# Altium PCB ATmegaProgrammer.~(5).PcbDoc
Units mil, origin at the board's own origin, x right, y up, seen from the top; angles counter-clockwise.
Board outline 6000 x 4000 mil, 2 copper layers (Top Layer, Bottom Layer); 9 components, 8 nets, 64 pads, 0 vias.
Unrouted connection lines stored in the file: 16.
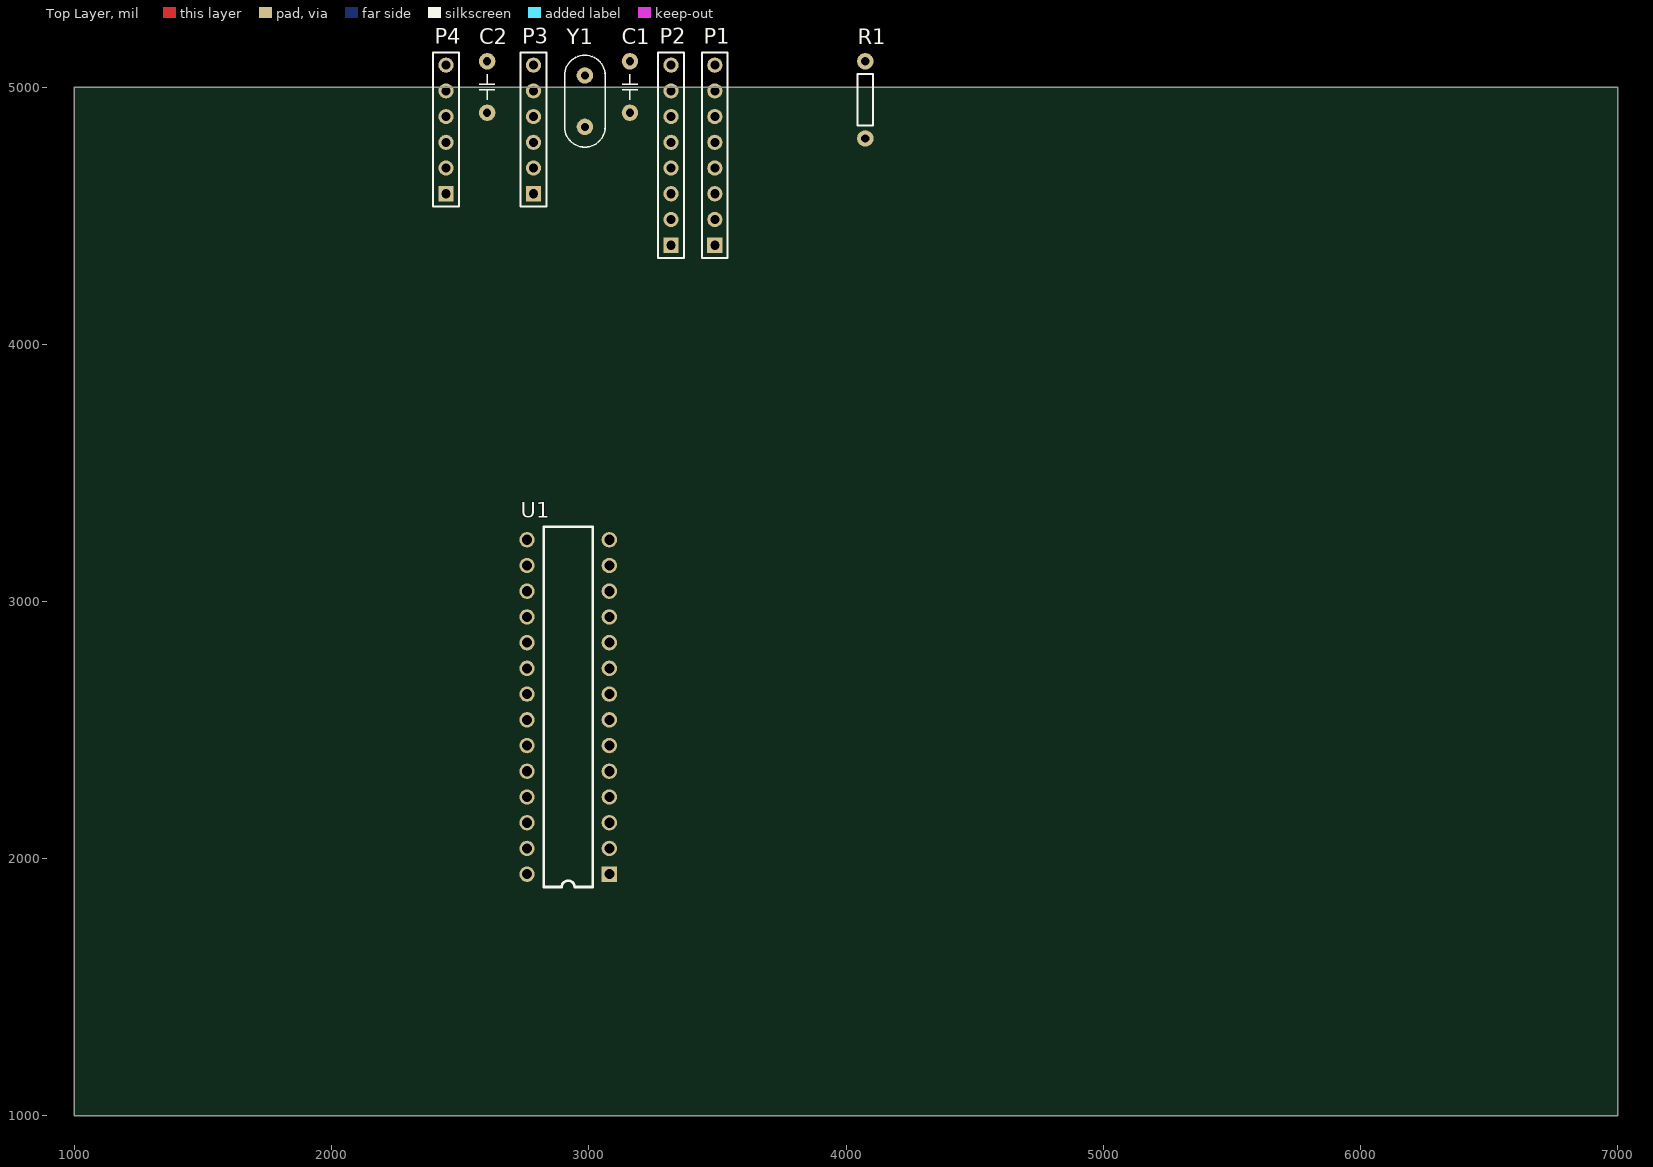
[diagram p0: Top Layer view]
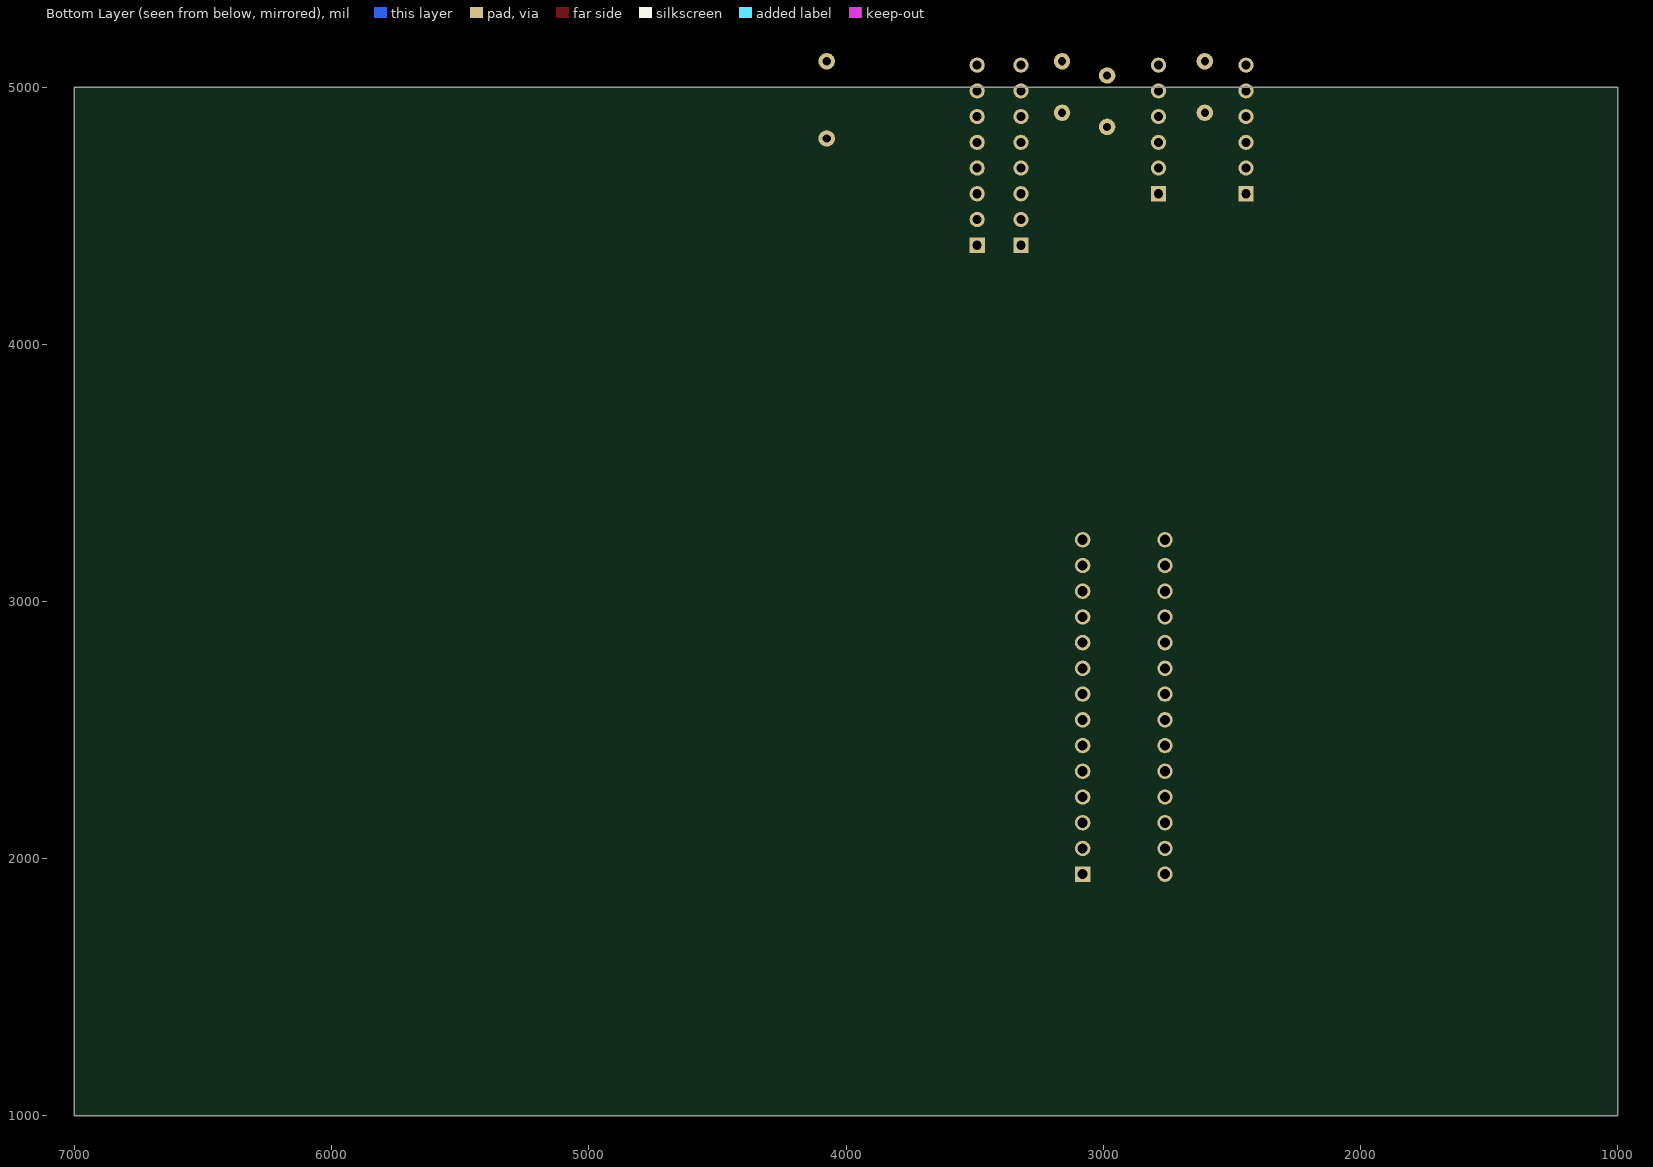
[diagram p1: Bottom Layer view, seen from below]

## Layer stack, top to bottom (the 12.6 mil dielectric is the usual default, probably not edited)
Top Layer: signal copper 1.4
Dielectric: dielectric 12.6, FR-4, Dk 4.8
Bottom Layer: signal copper 1.4

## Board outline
1000,1000 7000,1000 7000,5000 1000,5000

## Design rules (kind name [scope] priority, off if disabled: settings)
Clearance [All] p1: gap=10
PolygonConnect [All] p1: connectstyle=Relief reliefconductorwidth=10 reliefentries=4 polygonreliefangle="90 Angle"
RoomDefinition ATmegaProgrammer [InComponentClass('ATmegaProgrammer')] p1: confinementstyle=ConfineIn formatcopy=TRUE lockcomponents=FALSE outline 2385,3725 4145,3725 4145,5245 2385,5245
RoutingVias [All] p1: holewidth=28 width=50 viastyle="Through Hole" minholewidth=28 minwidth=50 maxholewidth=28 maxwidth=50
SilkscreenOverComponentPads [All] p1: minsilkscreentomaskgap=10
SolderMaskExpansion [All] p1: expansion=4
Width [All] p1: maxlimit=10 minlimit=10 preferedwidth=10
27 further rules are at their usual default settings.

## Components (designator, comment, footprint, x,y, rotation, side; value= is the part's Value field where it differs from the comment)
C1 "20pF" C200 3160,5000 r0 top
C2 "20pF" C200 2605,5000 r0 top
P1 "Header 8" HDR1X8 3490,4385 r90 top
P2 "Header 8" HDR1X8 3320,4385 r90 top
P3 "Header 6" HDR1X6 2785,4585 r90 top
P4 "Header 6" HDR1X6 2445,4585 r90 top
R1 "10k" AXIAL-0.3 4075,4950 r90 top
U1 "ATmega328" DIP28 3080,1940 r180 top
Y1 "16MHz" XTAL4-8 2985,4945 r90 top

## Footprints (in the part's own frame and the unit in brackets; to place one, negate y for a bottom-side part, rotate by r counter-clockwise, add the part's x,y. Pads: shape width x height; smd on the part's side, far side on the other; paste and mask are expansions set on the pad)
AXIAL-0.3 [mil] "0.3\" Resistor; 2 Leads"
  round 64 hole 31.5: 1(-150,0) 2(150,0)
  silkscreen extent -100,-30 100,30, body extent -161,-39 165,39, height 86
C200 [mil] "鹅溅筿甧竟"
  round 64 hole 31.5: 1(0,100) 2(0,-100)
  silkscreen extent -30,-50 30,50, body extent -41,-136 39,135, height 354
DIP28 [mil]
  rect 60x60 hole 39.37: 1(0,0)
  round 60 hole 39.37: 2(0,-100) 3(0,-200) 4(0,-300) 5(0,-400) 6(0,-500) 7(0,-600) 8(0,-700) 9(0,-800) 10(0,-900) 11(0,-1000) 12(0,-1100) 13(0,-1200) 14(0,-1300) 15(320,-1300) 16(320,-1200) 17(320,-1100) 18(320,-1000) 19(320,-900) 20(320,-800) 21(320,-700) 22(320,-600) 23(320,-500) 24(320,-400) 25(320,-300) 26(320,-200) 27(320,-100) 28(320,0)
  silkscreen extent 65,-1350 255,50, body extent 65,-1350 255,50, height 130
HDR1X6 [mm] "Connector; Header; 6 Position"
  rect 1.5x1.5 hole 0.9: 1(0,0)
  round 1.5 hole 0.9: 2(2.54,0) 3(5.08,0) 4(7.62,0) 5(10.16,0) 6(12.7,0)
  silkscreen extent -1.27,-1.27 13.97,1.27
HDR1X8 [mm] "Connector; Header; 8 Position"
  rect 1.5x1.5 hole 0.9: 1(0,0)
  round 1.5 hole 0.9: 2(2.54,0) 3(5.08,0) 4(7.62,0) 5(10.16,0) 6(12.7,0) 7(15.24,0) 8(17.78,0)
  silkscreen extent -1.27,-1.27 19.05,1.27
XTAL4-8 [mil]
  round 64 hole 31.5: 1(-100,0) 2(100,0)
  silkscreen extent -179,-79 179,79, body extent -178,-80 192,79, height 157

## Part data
C1 C2: library part Cap, "Capacitor"
P1 P2: "Header, 8-Pin"
P3 P4: "Header, 6-Pin"
R1: library part Res, "Resistor"
U1: "ATmega¨t¦C³æ´¹¤ù"
Y1: library part XTAL, "Crystal Oscillator"

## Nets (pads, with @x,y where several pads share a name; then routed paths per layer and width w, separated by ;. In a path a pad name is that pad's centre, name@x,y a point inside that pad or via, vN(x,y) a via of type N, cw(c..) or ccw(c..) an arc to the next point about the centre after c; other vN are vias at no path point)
GND: C1.1 C2.1 P4.4 U1.8 U1.22
MISO: P2.5 U1.18
MOSI: P2.4 U1.17
NetC1_2: C1.2 U1.10 Y1.2
NetC2_2: C2.2 U1.9 Y1.1
RESET: P2.3 R1.1 U1.1
SCK: P2.6 U1.19
VCC: P4.3 R1.2 U1.7 U1.20
pads on no net: P1.1 P1.2 P1.3 P1.4 P1.5 P1.6 P1.7 P1.8 P2.1 P2.2 P2.7 P2.8 P3.1 P3.2 P3.3 P3.4 P3.5 P3.6 P4.1 P4.2 P4.5 P4.6 U1.2 U1.3 U1.4 U1.5 U1.6 U1.11 U1.12 U1.13 U1.14 U1.15 U1.16 U1.21 U1.23 U1.24 U1.25 U1.26 U1.27 U1.28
